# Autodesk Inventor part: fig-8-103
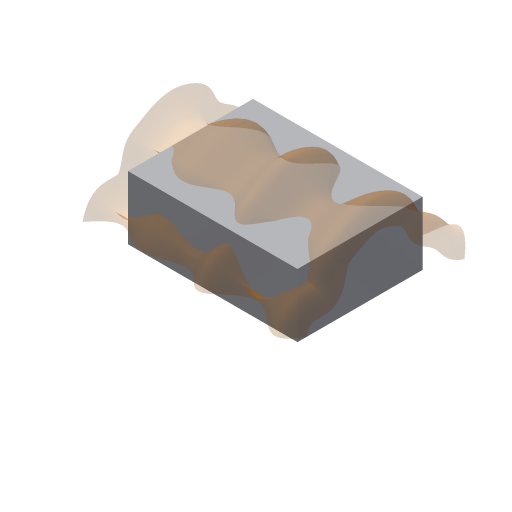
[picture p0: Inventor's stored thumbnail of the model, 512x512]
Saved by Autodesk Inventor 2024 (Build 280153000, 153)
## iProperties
Shininess: 64.0
Length Units: 11269
Angle Units: 11279
Time Units: 11290
Mass Units: 11283
Length Display Precision: 3
Angle Display Precision: 2
Compacted: True
Part Number: fig-8-103
Document SubType Name: Modeling
Created: 2002-12
Designer: deepak
Density: 1 g/cm^3
Material: Generic
Appearance: Aluminum - Flat
Density: 0.0
Volumn: 0.0
Area: 0.0
PropertySet Name: Model Information
Control State: 0
Master: False
Checked Out: False
Author: deepak
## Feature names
1. Extrusion1
## Parameters: d0 = 25 mm, d1 = 0, d2 = 0, d3 = 0
